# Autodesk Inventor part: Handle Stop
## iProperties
Created: 2002-02
Part Number: Handle Stop
Document SubType Name: Modeling
Designer: ***
Control State: 0
Master: False
Checked Out: False
Shininess: 77.0
Length Units: 11269
Angle Units: 11279
Time Units: 11290
Mass Units: 11283
Length Display Precision: 3
Angle Display Precision: 2
Compacted: True
Density: 0.0
Volumn: 0.0
Area: 0.0
PropertySet Name: Model Information
Author: ***
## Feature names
1. Revolution1
